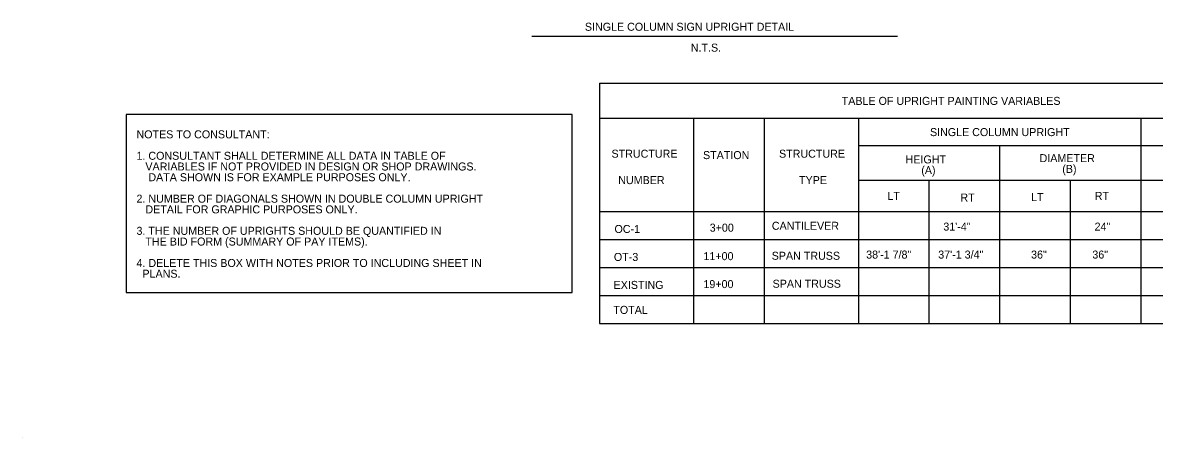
# Model space of a CAD drawing. Extents: x 10268852 to 10269008, y 2142584 to 2142686.
# Drawn here: x 10268851.6 to 10268947.8, y 2142583.9 to 2142619.1 of the extents above; entities that cross this region are included whole.
import ezdxf

# ---------------------------------------------------------------- set-up
doc = ezdxf.new("R2010")
doc.units = 0
for name, color, linetype in [('AdhocPoint_dp', 7, 'Continuous'), ('SignDetail', 7, 'Continuous'), ('TextAlert', 7, 'Continuous'), ('TextDetails', 7, 'Continuous'), ('TextTables', 7, 'Continuous')]:
    doc.layers.add(name, color=color, linetype=linetype)

msp = doc.modelspace()

# ---------------------------------------------------------------- linework, layer by layer
at = {"layer": 'AdhocPoint_dp'}
msp.add_line((10268851.561, 2142583.858), (10268851.561, 2142583.858), dxfattribs=at)
at = {"layer": 'TextAlert'}
msp.add_lwpolyline([(10268860.358, 2142596.166), (10268898.277, 2142596.166), (10268898.277, 2142611.286), (10268860.358, 2142611.286)], close=True, dxfattribs=at)
at = {"layer": 'TextDetails'}
msp.add_line((10268894.854, 2142617.945), (10268925.92, 2142617.945), dxfattribs=at)
at = {"layer": 'TextTables'}
for p, q in [((10268900.595, 2142613.976), (10269000.595, 2142613.976)), ((10268900.595, 2142613.976), (10268900.595, 2142593.534)), ((10268900.595, 2142610.976), (10269000.595, 2142610.976)), ((10268908.595, 2142610.976), (10268908.595, 2142593.534)), ((10268914.595, 2142610.976), (10268914.595, 2142593.534)), ((10268922.595, 2142610.976), (10268922.595, 2142593.534)), ((10268946.595, 2142610.976), (10268946.595, 2142593.534)), ((10268922.595, 2142608.66), (10268994.595, 2142608.66)), ((10268934.595, 2142608.66), (10268934.595, 2142593.534)), ((10268922.595, 2142605.725), (10268994.595, 2142605.725)), ((10268928.595, 2142605.725), (10268928.595, 2142593.534)), ((10268940.595, 2142605.725), (10268940.595, 2142593.534)), ((10268900.595, 2142603.042), (10269000.595, 2142603.042)), ((10268900.595, 2142600.665), (10269000.595, 2142600.665)), ((10268900.595, 2142598.288), (10269000.595, 2142598.288)), ((10268900.595, 2142595.911), (10269000.595, 2142595.911)), ((10268900.595, 2142593.534), (10269000.595, 2142593.534))]:
    msp.add_line(p, q, dxfattribs=at)

# ---------------------------------------------------------------- texts
at = {"layer": 'SignDetail'}
msp.add_text('TOTAL', height=0.68, dxfattribs=at).set_placement((10268901.77, 2142594.352))
at = {"layer": 'TextAlert'}
for s, p in [('NOTES TO CONSULTANT:', (10268861.238, 2142609.273)), ('1. CONSULTANT SHALL DETERMINE ALL DATA IN TABLE OF', (10268861.238, 2142607.451)), ('   VARIABLES IF NOT PROVIDED IN DESIGN OR SHOP DRAWINGS.', (10268861.238, 2142606.54)), ('    DATA SHOWN IS FOR EXAMPLE PURPOSES ONLY.', (10268861.238, 2142605.628)), ('2. NUMBER OF DIAGONALS SHOWN IN DOUBLE COLUMN UPRIGHT', (10268861.238, 2142603.806)), ('   DETAIL FOR GRAPHIC PURPOSES ONLY.', (10268861.238, 2142602.895)), ('3. THE NUMBER OF UPRIGHTS SHOULD BE QUANTIFIED IN', (10268861.238, 2142601.072)), ('   THE BID FORM (SUMMARY OF PAY ITEMS). ', (10268861.238, 2142600.161)), ('4. DELETE THIS BOX WITH NOTES PRIOR TO INCLUDING SHEET IN', (10268861.238, 2142598.339)), ('  PLANS.', (10268861.238, 2142597.427))]:
    msp.add_text(s, height=0.68, dxfattribs=at).set_placement(p)
at = {"layer": 'TextDetails'}
for s, p in [('SINGLE COLUMN SIGN UPRIGHT DETAIL', (10268899.352, 2142618.416)), ('N.T.S.', (10268908.353, 2142616.64))]:
    msp.add_text(s, height=0.68, dxfattribs=at).set_placement(p)
at = {"layer": 'TextTables'}
for s, p in [('                                     TABLE OF UPRIGHT PAINTING VARIABLES', (10268911.835, 2142612.115)), ('SINGLE COLUMN UPRIGHT', (10268928.685, 2142609.463)), ('STRUCTURE', (10268901.616, 2142607.627)), ('STATION', (10268909.392, 2142607.508)), ('STRUCTURE', (10268915.854, 2142607.627)), ('HEIGHT', (10268926.614, 2142607.142)), ('DIAMETER', (10268938, 2142607.248)), ('(A)', (10268927.944, 2142606.231)), ('(B)', (10268939.928, 2142606.337)), ('NUMBER', (10268902.189, 2142605.382)), ('TYPE', (10268917.554, 2142605.382)), ('LT', (10268925.068, 2142604.04)), ('RT', (10268931.267, 2142603.903)), ('LT', (10268937.281, 2142603.94)), ('RT', (10268942.685, 2142604.04)), ('CANTILEVER', (10268915.243, 2142601.501)), ('31\'-4"', (10268929.819, 2142601.431)), ('24"', (10268942.675, 2142601.431)), ('OC-1', (10268901.869, 2142601.229)), ('3+00', (10268909.961, 2142601.341)), ('OT-3', (10268901.817, 2142598.852)), ('11+00', (10268909.428, 2142598.92)), ('SPAN TRUSS', (10268915.23, 2142598.953)), ('38\'-1 7/8"', (10268923.261, 2142599.054)), ('37\'-1 3/4"', (10268929.387, 2142599.054)), ('36"', (10268937.279, 2142599.054)), ('36"', (10268942.485, 2142599.054)), ('19+00', (10268909.428, 2142596.543)), ('SPAN TRUSS', (10268915.306, 2142596.575)), ('EXISTING', (10268901.793, 2142596.475))]:
    msp.add_text(s, height=0.68, dxfattribs=at).set_placement(p)

doc.saveas('drawing.dxf')
